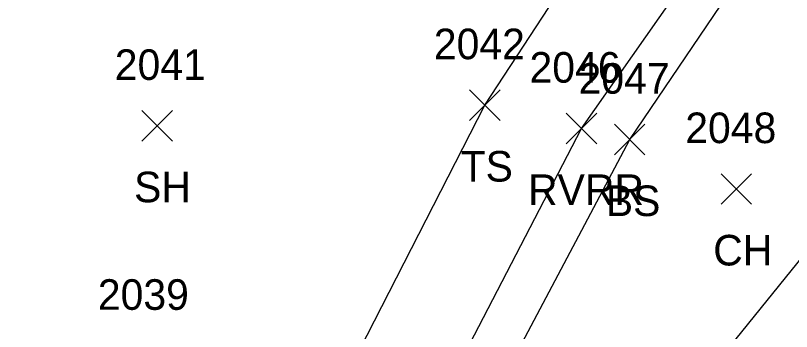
# Model space of a CAD drawing. Extents: x 1600395 to 1603269, y 874955 to 877143.
# Drawn here: x 1601757.4 to 1601808.1, y 875274.8 to 875295.5 of the extents above; entities that cross this region are included whole.
import ezdxf

# ---------------------------------------------------------------- set-up
doc = ezdxf.new("R2010")
doc.units = 0
for name, color, linetype in [('L_A', 7, 'Continuous'), ('L_I', 7, 'Continuous'), ('L_TIC', 7, 'Continuous'), ('LAWE', 7, 'Continuous'), ('LELB', 7, 'Continuous')]:
    doc.layers.add(name, color=color, linetype=linetype)

msp = doc.modelspace()

# ---------------------------------------------------------------- linework, layer by layer
at = {"layer": 'L_TIC'}
for points in [[(1601787.08, 875288.651), (1601789.08, 875290.651)], [(1601789.08, 875288.651), (1601787.08, 875290.651)], [(1601765.663, 875287.297), (1601767.663, 875289.297)], [(1601767.663, 875287.297), (1601765.663, 875289.297)], [(1601793.383, 875287.119), (1601795.383, 875289.119)], [(1601795.383, 875287.119), (1601793.383, 875289.119)], [(1601796.538, 875286.395), (1601798.538, 875288.395)], [(1601798.538, 875286.395), (1601796.538, 875288.395)], [(1601803.509, 875283.165), (1601805.509, 875285.165)], [(1601805.509, 875283.165), (1601803.509, 875285.165)]]:
    msp.add_lwpolyline(points, dxfattribs=at)
at = {"layer": 'LAWE'}
msp.add_lwpolyline([(1601691.608, 874961.829), (1601690.191, 874993.063), (1601689.233, 875017.016), (1601693.176, 875046.242), (1601698.322, 875069.371), (1601704.726, 875096.639), (1601712.321, 875125.386), (1601726.379, 875151.584), (1601742.355, 875184.332), (1601749.838, 875201.821), (1601757.17, 875214.811), (1601763.474, 875228.289), (1601769.619, 875241.931), (1601778.226, 875255.274), (1601780.685, 875261.68), (1601794.383, 875288.119), (1601816.126, 875319.133), (1601836.101, 875339.545), (1601856.898, 875374.373), (1601871.663, 875400.698), (1601886.602, 875430.708)], dxfattribs=at)
at = {"layer": 'LELB'}
for points in [[(1601782.885, 875259.703), (1601797.538, 875287.395), (1601818.14, 875317.833), (1601840.048, 875340.046), (1601859.666, 875369.319), (1601874.59, 875400.481), (1601889.553, 875430.007), (1601905.964, 875461.656), (1601915.863, 875481.253), (1601936.763, 875517.324), (1601948.527, 875545.356), (1601941.42, 875586.609)], [(1601796.014, 875263.88), (1601812.137, 875283.829), (1601829.745, 875313.481), (1601858.71, 875336.21), (1601879.525, 875354.558)], [(1601764.355, 875260.518), (1601777.022, 875268.044), (1601788.08, 875289.651), (1601798.545, 875305.666), (1601807.324, 875318.655)]]:
    msp.add_lwpolyline(points, dxfattribs=at)

# ---------------------------------------------------------------- texts
at = {"layer": 'L_A'}
for s, p in [('TS', (1601786.489, 875284.651)), ('SH', (1601765.151, 875283.297)), ('RVRR', (1601790.895, 875283.119)), ('BS', (1601795.979, 875282.395)), ('CH', (1601802.997, 875279.165))]:
    msp.add_text(s, height=2, dxfattribs=at).set_placement(p)
at = {"layer": 'L_I'}
for s, p in [('2042', (1601784.741, 875292.651)), ('2041', (1601763.891, 875291.297)), ('2046', (1601790.99, 875291.119)), ('2047', (1601794.199, 875290.395)), ('2048', (1601801.171, 875287.165)), ('2039', (1601762.785, 875276.264))]:
    msp.add_text(s, height=2, dxfattribs=at).set_placement(p)

doc.saveas('drawing.dxf')
